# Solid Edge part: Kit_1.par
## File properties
Sűrűség: 0,000 kg/m^3
Pontosság: 0,990
Author: bmolnar
Last saved by: psaghy
Revision: 78
Username: bmolnar
Dokumentum tartalom típus: 0
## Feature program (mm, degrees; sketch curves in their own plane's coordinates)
base feature "unnamed BaseFeature 1"
sketch for "Furat_1" plane through (0, 0, 39) normal (0, 0, 1) x-axis (0, -1, 0)
  hole centre (-23.25, -23.25) bore radius 3.3235
hole "Furat_1" nominal diameter 8 finite  VBottomAngle = 118 deg
sketch for "unnamed Hole 1" plane through (0, 0, 39) normal (0, 0, 1) x-axis (0, -1, 0)
  hole centre (-23.25, 23.25) bore radius 3.3235
hole "unnamed Hole 1" finite
sketch for "unnamed Hole 2" plane through (0, 0, 39) normal (0, 0, 1) x-axis (0, -1, 0)
  hole centre (23.25, 23.25) bore radius 3.3235
hole "unnamed Hole 2" finite
sketch for "unnamed Hole 3" plane through (0, 0, 39) normal (0, 0, 1) x-axis (0, -1, 0)
  hole centre (23.25, -23.25) bore radius 3.3235
hole "unnamed Hole 3" finite
pattern "unnamed Pattern 1" of "Furat_1", "unnamed Hole 1", "unnamed Hole 2", "unnamed Hole 3"
sketch for "Furat_5" plane through (32.5, 0.0003, 21.2488) normal (1, 0, 0) x-axis (0, 0, 1)
hole "Furat_5" diameter 13.157 finite  ThreadDepth = 10 mm
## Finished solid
Body 1: solid body, 411 faces, 942 edges, 585 vertices, 7 internal voids.
  Faces by surface: plane 146, cylinder 129, torus 46, cone 37, sphere 23, spline 21, swept 9
  Edges by curve: line 347, curve on surface 286, circle 284, spline 25
Bounding box of the edges (mm; curved faces can reach further): 65.000 x 65.000 x 35.000, from (-32.5, -32.5, 8) to (32.5002, 32.5, 43).
Cylindrical faces by radius (mm): R0.3125 x1, R0.3838 x1, R0.4089 x1, R0.4253 x1, R0.4408 x1, R0.5 x8, R0.5003 x1, R0.5483 x1, R0.5961 x1, R0.615 x1, R0.6311 x1, R0.6362 x1, R0.652 x1, R0.6792 x1, R0.73 x1, R0.7378 x1, R0.7396 x1, R0.9114 x1, R1 x20, R1.0004 x7, R1.001 x6, R1.0014 x8, R1.0015 x1, R1.0026 x1, R1.0394 x1, R1.0539 x1, R1.0734 x1, R1.0987 x1, R1.1871 x1, R1.2561 x1, R1.2722 x2, R1.3621 x1, R1.3711 x1, R1.4 x1, R1.7143 x1, R3.3235 x8, R4 x4, R4.15 x4, R4.5 x1, R5 x2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
Conical faces (half-angle, radius in mm at the cone's reference point): 0.5 deg R18.5 x4, 0.5 deg R22.25 x4, 30 deg R5.1443 x1, 30 deg R11.8557 x1, 31.4296 deg R28.625 x4, 45 deg R2.75 x1, 45 deg R2.825 x1, 45 deg R4.3 x8, 45 deg R6.35 x8, 45 deg R6.72 x1, 59 deg R3.3235 x4
Toroidal faces (ring radius, tube radius in mm): R0.4909 r0.5044 x1, R0.5094 r0.5004 x1, R0.8674 r0.5067 x1, R1.4976 r0.5003 x6, R4.3 r0.3 x4, R4.7 r0.3 x1, R6.45 r0.2 x4, R7.15 r0.5 x4, R9.5 r0.5 x1, R9.75 r0.5 x2, R13.9897 r0.5062 x1, R19.4739 r1 x1, R19.4913 r1 x3, R19.5 r0.5 x1, R20.5 r0.5 x1, R21.2587 r1 x3, R21.2761 r1 x1, R27.25 r1 x3, R31.75 r1 x6, R33.3108 r1 x1
Spherical faces by radius (mm): R0.5 x1, R1 x22
Planar faces by outward normal: +x 23, +y 9, +z 31, -x 5, -y 8, -z 21, oblique 49
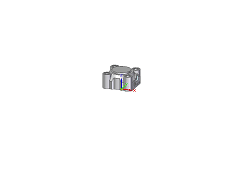
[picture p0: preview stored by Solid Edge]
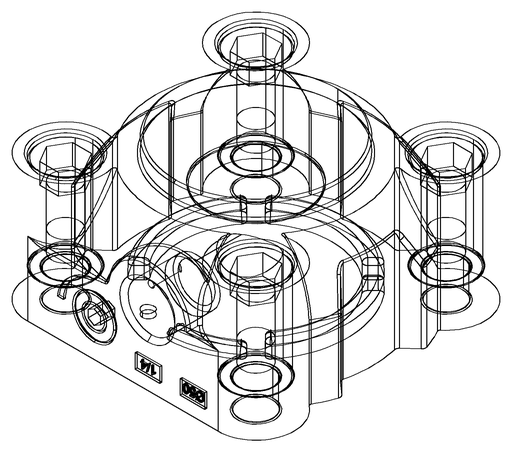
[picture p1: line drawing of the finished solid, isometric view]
